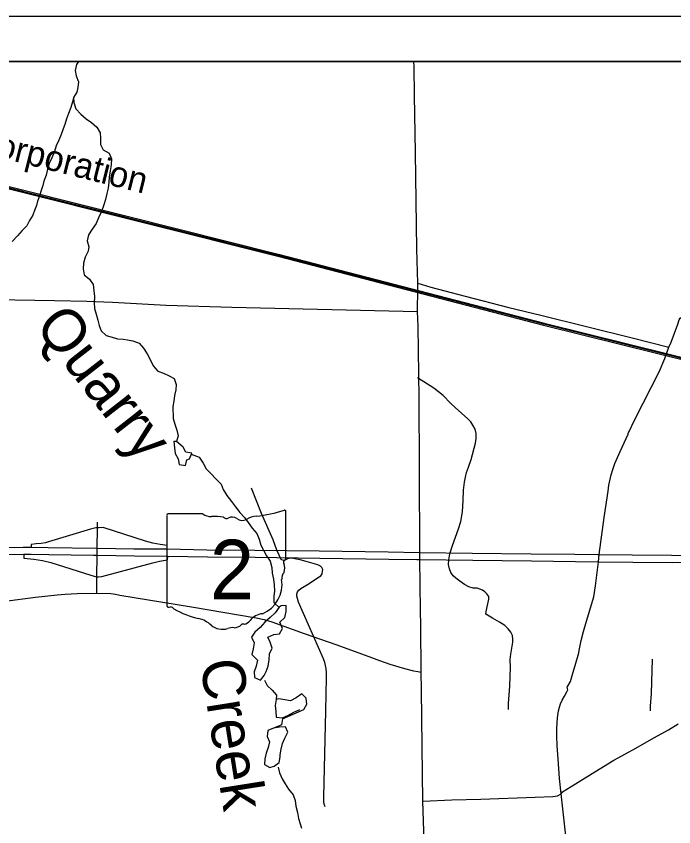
# Model space of a CAD drawing. Extents: x 0 to 34, y 0 to 22.
# Drawn here: x 10.012 to 11.47, y 8.768 to 10.565 of the extents above; entities that cross this region are included whole.
import ezdxf

# ---------------------------------------------------------------- set-up
doc = ezdxf.new("R2010")
doc.units = 0
for name, color, linetype in [('GM_X_City_Street', 7, 'Continuous'), ('GM_X_Corporation', 7, 'Continuous'), ('GM_X_County_Road', 7, 'Continuous'), ('GM_X_Interchange_Ramps', 7, 'Continuous'), ('GM_X_Minor_Lake', 7, 'Continuous'), ('GM_X_Minor_River', 7, 'Continuous'), ('GM_X_Minor_River_Text', 7, 'Continuous'), ('GM_X_Rail_Line', 7, 'Continuous'), ('GM_X_Rail_Line_Text', 7, 'Continuous'), ('GM_X_State_Location', 7, 'Continuous'), ('GM_X_State_Route', 7, 'Continuous'), ('GM_X_State_Shield', 7, 'Continuous'), ('GM_X_Township_Road', 7, 'Continuous'), ('SH_Cut_Line', 7, 'Continuous'), ('SH_Data', 7, 'Continuous')]:
    doc.layers.add(name, color=color, linetype=linetype)

msp = doc.modelspace()

# ---------------------------------------------------------------- linework, layer by layer
at = {"layer": 'GM_X_City_Street'}
for points in [[(11.103, 9.028), (11.1032, 9.0413), (11.1062, 9.0799), (11.1074, 9.1217), (11.1072, 9.1391), (11.1084, 9.1504), (11.1109, 9.164), (11.1131, 9.177), (11.1131, 9.1841), (11.1123, 9.1917), (11.1087, 9.1996), (11.1028, 9.207), (11.0949, 9.2141), (11.0831, 9.2217), (11.0681, 9.2308), (11.0531, 9.2397), (11.0535, 9.2453), (11.0578, 9.262), (11.0597, 9.2724), (11.0595, 9.2785), (11.0556, 9.2842), (11.0511, 9.2886), (11.046, 9.2923), (11.0337, 9.2972), (11.0253, 9.2972), (11.0155, 9.2999), (11.0059, 9.3053), (10.9951, 9.3122), (10.9865, 9.3188), (10.9808, 9.3245), (10.9757, 9.3318), (10.9725, 9.3395), (10.9705, 9.3493), (10.971, 9.3594), (10.9732, 9.3731), (10.9791, 9.3916), (10.9924, 9.4287), (10.9973, 9.4444), (11.001, 9.4658), (11.0027, 9.4914), (11.0039, 9.514), (11.0059, 9.5322), (11.0079, 9.5427), (11.0103, 9.5535), (11.0143, 9.5649), (11.0202, 9.5818), (11.0298, 9.6184), (11.0315, 9.6288), (11.0317, 9.6401), (11.0295, 9.6492), (11.0241, 9.6583), (11.0197, 9.6659), (11.0133, 9.6725), (10.9849, 9.6977), (10.9757, 9.7064), (10.9585, 9.7241), (10.9376, 9.7401), (10.9013, 9.7633)], [(10.6972, 8.8122), (10.695, 8.8185), (10.6942, 8.8234), (10.6941, 8.8348), (10.6987, 9.0253), (10.7001, 9.0991), (10.6999, 9.1104), (10.6994, 9.1185), (10.6977, 9.1254), (10.696, 9.1323), (10.693, 9.1406), (10.6603, 9.2156), (10.6382, 9.2662), (10.6357, 9.2738), (10.6343, 9.279), (10.6345, 9.2834), (10.6353, 9.2886), (10.6384, 9.2923), (10.6434, 9.296), (10.6613, 9.3075), (10.6797, 9.3198), (10.6871, 9.3242), (10.6901, 9.3289), (10.691, 9.3343), (10.6918, 9.3385), (10.6896, 9.3429), (10.6866, 9.3459), (10.681, 9.349), (10.6705, 9.3519), (10.6548, 9.3563), (10.6419, 9.3599), (10.6294, 9.3621), (10.6232, 9.3631), (10.6185, 9.3633), (10.6136, 9.3618), (10.6094, 9.3596), (10.6043, 9.3582), (10.6011, 9.3594), (10.5991, 9.3608), (10.5969, 9.3648), (10.5947, 9.3702), (10.59, 9.381), (10.5817, 9.4039), (10.5561, 9.4621), (10.5338, 9.5189)], [(11.4184, 9.0248), (11.4184, 9.0352), (11.4203, 9.0637), (11.4228, 9.1396)]]:
    msp.add_lwpolyline(points, dxfattribs=at)
at = {"layer": 'GM_X_Corporation'}
msp.add_lwpolyline([(12.0462, 8.3651), (12.0135, 9.4352), (12.0067, 9.6607), (11.5211, 9.7826), (11.5392, 9.8926), (11.8108, 9.8914), (11.7983, 10.4305), (11.9902, 10.4375), (11.9896, 10.4647), (7.3135, 10.4647)], dxfattribs=at)
at = {"layer": 'GM_X_County_Road'}
for p, q in [((10.902, 9.9603), (10.902, 9.9729)), ((10.9018, 9.9099), (10.902, 9.9603)), ((10.9094, 9.1109), (10.9087, 9.2133))]:
    msp.add_line(p, q, dxfattribs=at)
for points in [[(10.902, 9.9729), (10.9001, 10.0483), (10.8971, 10.2629), (10.8947, 10.389), (10.8939, 10.4522), (10.8937, 10.4647)], [(10.902, 9.9729), (10.9315, 9.9638), (11.0075, 9.9439), (11.1043, 9.9193), (11.1751, 9.9018), (11.3776, 9.8519), (11.4209, 9.8404), (11.4583, 9.8308), (11.4637, 9.8421), (11.4784, 9.8822), (11.4819, 9.8915), (11.4838, 9.8954), (11.4875, 9.8977), (11.4912, 9.8986), (11.4971, 9.8994), (11.5037, 9.8991)], [(9.5381, 9.9488), (9.7465, 9.9426), (9.9213, 9.9377), (10.0971, 9.9343), (10.1688, 9.9331), (10.2256, 9.9306), (10.3448, 9.924), (10.4898, 9.9195), (10.9018, 9.9099)], [(10.9063, 9.5564), (10.9063, 9.563), (10.9055, 9.7182), (10.903, 9.8777), (10.9018, 9.9099)], [(10.9068, 9.3605), (10.9067, 9.3763), (10.9063, 9.5564)], [(10.1912, 9.2861), (10.1909, 9.3224), (10.1914, 9.3701), (10.1916, 9.3858), (10.1922, 9.4305), (10.1926, 9.4434)], [(10.9087, 9.2133), (10.9084, 9.2485), (10.9068, 9.3605)], [(10.9133, 8.8248), (10.9118, 8.9464), (10.9104, 9.0716), (10.9094, 9.1109)], [(10.9274, 8.1427), (10.9276, 8.2181), (10.9246, 8.3546), (10.9237, 8.443), (10.9207, 8.5401), (10.9187, 8.6294), (10.9172, 8.7146), (10.9133, 8.8248)]]:
    msp.add_lwpolyline(points, dxfattribs=at)
at = {"layer": 'GM_X_Interchange_Ramps'}
for points in [[(10.1922, 9.4305), (10.1884, 9.4305), (10.177, 9.4279), (10.0838, 9.3994), (10.0772, 9.3978), (10.0676, 9.3963), (10.0562, 9.3952), (10.0454, 9.3937), (10.0454, 9.3878)], [(10.3468, 9.3839), (10.3468, 9.3912), (10.331, 9.3941), (10.3152, 9.3969), (10.299, 9.4013), (10.2047, 9.4314), (10.1961, 9.4309), (10.1922, 9.4305)], [(10.0289, 9.3724), (10.0291, 9.3638), (10.0514, 9.3614), (10.0704, 9.3586), (10.0889, 9.3537), (10.1779, 9.3259), (10.1849, 9.3235), (10.1909, 9.3224)], [(10.1909, 9.3224), (10.1946, 9.3222), (10.2023, 9.3226), (10.315, 9.3531), (10.3297, 9.357), (10.3478, 9.3594), (10.348, 9.3681)]]:
    msp.add_lwpolyline(points, dxfattribs=at)
at = {"layer": 'GM_X_Minor_Lake'}
for points in [[(10.3676, 9.6223), (10.3619, 9.6219), (10.3631, 9.6082), (10.3648, 9.5956), (10.3709, 9.5835), (10.3737, 9.5714), (10.3874, 9.5688), (10.3907, 9.5814)], [(10.3676, 9.6223), (10.3619, 9.6219), (10.3631, 9.6082), (10.3648, 9.5956), (10.3709, 9.5835), (10.3737, 9.5714), (10.3874, 9.5688), (10.3907, 9.5814)], [(10.3907, 9.5814), (10.396, 9.5837), (10.4012, 9.5963), (10.3883, 9.5985), (10.3821, 9.6095), (10.3675, 9.6223)], [(10.3907, 9.5814), (10.396, 9.5837), (10.4012, 9.5963), (10.3883, 9.5985), (10.3821, 9.6095), (10.3676, 9.6223)], [(10.5998, 9.258), (10.5952, 9.2549), (10.5862, 9.2426), (10.5749, 9.2319), (10.5636, 9.2219), (10.5527, 9.21), (10.541, 9.1996), (10.5335, 9.1881), (10.5393, 9.176), (10.5375, 9.1626), (10.5345, 9.1497), (10.5468, 9.1372), (10.5442, 9.1243), (10.5394, 9.1113), (10.5403, 9.0987), (10.554, 9.0928), (10.5619, 9.1035)], [(10.5956, 9.2533), (10.5952, 9.2549), (10.5862, 9.2426), (10.5749, 9.2319), (10.5636, 9.2219), (10.5527, 9.21), (10.541, 9.1996), (10.5335, 9.1881), (10.5393, 9.176), (10.5375, 9.1626), (10.5345, 9.1497), (10.5468, 9.1372), (10.5442, 9.1243), (10.5394, 9.1113), (10.5403, 9.0987), (10.554, 9.0928), (10.5619, 9.1035)], [(10.5619, 9.1035), (10.5664, 9.1123), (10.5709, 9.1241), (10.5726, 9.1378), (10.5733, 9.1515), (10.5793, 9.1642), (10.5754, 9.1771), (10.5696, 9.1884), (10.5832, 9.1939), (10.5957, 9.1955), (10.6021, 9.2077), (10.5963, 9.2218), (10.6076, 9.2321), (10.6105, 9.2451), (10.6108, 9.2588), (10.5998, 9.258)], [(10.5892, 9.0596), (10.5886, 9.0501), (10.586, 9.0367), (10.5876, 9.0238), (10.5885, 9.0109), (10.6022, 9.0099), (10.6143, 9.0149), (10.6276, 9.0219), (10.6408, 9.0277)], [(10.6169, 9.0137), (10.6499, 9.0282), (10.6563, 9.0397), (10.6547, 9.0534), (10.6451, 9.0624), (10.633, 9.0539), (10.6205, 9.047), (10.6076, 9.0491), (10.5946, 9.0517)], [(10.6022, 9.0072), (10.6499, 9.0282), (10.6563, 9.0397), (10.6547, 9.0534), (10.6451, 9.0624), (10.633, 9.0539), (10.6205, 9.047), (10.6076, 9.0491), (10.5946, 9.0517)], [(10.5946, 9.0517), (10.5886, 9.0501), (10.586, 9.0367), (10.5876, 9.0238), (10.5885, 9.0109), (10.6022, 9.0099), (10.6169, 9.0137)], [(10.6004, 8.9943), (10.5955, 8.9919), (10.5822, 8.9869), (10.5697, 8.9814), (10.5687, 8.9685), (10.5737, 8.9563), (10.5708, 8.9441), (10.5664, 8.9312), (10.563, 8.919), (10.5628, 8.906), (10.5742, 8.8996), (10.5837, 8.9024), (10.595, 8.9109), (10.5976, 8.9231)], [(10.5955, 8.9885), (10.5822, 8.9869), (10.5697, 8.9814), (10.5687, 8.9685), (10.5737, 8.9563), (10.5708, 8.9441), (10.5664, 8.9312), (10.563, 8.919), (10.5628, 8.906), (10.5742, 8.8996), (10.5837, 8.9024), (10.595, 8.9109), (10.5976, 8.9231)], [(10.5976, 8.9231), (10.5972, 8.9276), (10.5993, 8.9402), (10.6023, 8.9524), (10.6079, 8.9643), (10.6139, 8.9776), (10.6092, 8.9894), (10.5955, 8.9885)]]:
    msp.add_lwpolyline(points, dxfattribs=at)
at = {"layer": 'GM_X_Minor_River'}
for points in [[(10.1505, 10.4647), (10.146, 10.4578), (10.1426, 10.4441), (10.145, 10.4323), (10.1501, 10.4194), (10.149, 10.4065), (10.1465, 10.3966), (10.139, 10.3847)], [(10.139, 10.3847), (10.1371, 10.3748), (10.1334, 10.3626), (10.1282, 10.3492), (10.1238, 10.337), (10.1201, 10.3244), (10.116, 10.3149), (10.1119, 10.3026), (10.107, 10.29), (10.1011, 10.2774), (10.0974, 10.2652), (10.0914, 10.2507), (10.085, 10.2381), (10.0817, 10.2255), (10.0784, 10.2125), (10.0736, 10.1988), (10.071, 10.1892), (10.0669, 10.1759), (10.0636, 10.1656), (10.0595, 10.1549), (10.0569, 10.1454), (10.0524, 10.1339), (10.0487, 10.124), (10.042, 10.1121), (10.0356, 10.1003), (10.0251, 10.0899), (10.0153, 10.078), (10.0036, 10.065)], [(10.139, 10.3847), (10.1398, 10.3731), (10.1445, 10.3593), (10.1552, 10.3479), (10.1675, 10.3374), (10.1793, 10.3291), (10.1908, 10.3186), (10.1985, 10.3065), (10.199, 10.2943), (10.1987, 10.2806), (10.2053, 10.2685), (10.2183, 10.2614), (10.2237, 10.2485), (10.223, 10.2355), (10.2201, 10.2218), (10.2183, 10.2081), (10.2173, 10.1967), (10.2159, 10.1837), (10.2133, 10.1715), (10.21, 10.1585), (10.2063, 10.1463), (10.2015, 10.1322), (10.1944, 10.1181), (10.1891, 10.1051), (10.1805, 10.0928), (10.1726, 10.0802), (10.1697, 10.0672), (10.1728, 10.0536), (10.1718, 10.044), (10.165, 10.031), (10.161, 10.0177), (10.1603, 10.0047), (10.1631, 9.9918), (10.1749, 9.982), (10.1827, 9.9699), (10.1843, 9.9559), (10.1855, 9.9433), (10.1853, 9.9296), (10.1857, 9.9167), (10.1893, 9.9045), (10.1932, 9.8913), (10.1963, 9.8795), (10.2002, 9.867), (10.2117, 9.8572), (10.2247, 9.8531), (10.2365, 9.8498), (10.249, 9.8488), (10.2585, 9.8473), (10.2707, 9.8452), (10.2844, 9.8403), (10.2944, 9.829), (10.3025, 9.8161), (10.3095, 9.8021), (10.3156, 9.79), (10.326, 9.7783), (10.3386, 9.7735), (10.3512, 9.7679), (10.3623, 9.7615), (10.3669, 9.7486), (10.3659, 9.7368), (10.3629, 9.7242), (10.3615, 9.7113), (10.3597, 9.6998), (10.3599, 9.6732), (10.3635, 9.6607), (10.3685, 9.6474), (10.3713, 9.6345), (10.3676, 9.6223)], [(10.4002, 9.594), (10.4177, 9.587), (10.4269, 9.5741), (10.4335, 9.5612), (10.4442, 9.5503), (10.4549, 9.539), (10.4668, 9.5277), (10.4711, 9.5155), (10.4788, 9.5027), (10.4896, 9.4891), (10.4984, 9.4774), (10.508, 9.4649), (10.518, 9.4539), (10.5264, 9.4422), (10.5353, 9.4301), (10.5453, 9.418), (10.5507, 9.4055), (10.5546, 9.3926), (10.5669, 9.3684), (10.575, 9.3567), (10.5786, 9.343), (10.5798, 9.3304), (10.5826, 9.3168), (10.5842, 9.3042), (10.5847, 9.2913), (10.5829, 9.2783), (10.583, 9.2654), (10.5956, 9.2533)], [(10.5624, 9.0932), (10.5682, 9.0815), (10.5793, 9.0709), (10.5892, 9.0596)], [(10.6022, 9.0072), (10.6004, 8.9943)], [(10.5925, 8.9002), (10.5956, 8.8873), (10.6014, 8.8744), (10.6083, 8.863), (10.6157, 8.8513), (10.6264, 8.8392), (10.6307, 8.826), (10.6323, 8.8134), (10.6359, 8.7994), (10.6382, 8.7865), (10.6414, 8.7743), (10.6445, 8.7648)]]:
    msp.add_lwpolyline(points, dxfattribs=at)
at = {"layer": 'GM_X_Rail_Line'}
for points in [[(8.873, 10.4647), (9.6892, 10.2593), (10.5917, 10.0331), (11.1811, 9.8802), (12.0186, 9.6724), (12.8863, 9.4545), (13.1526, 9.3886), (13.8266, 9.2172), (14.1135, 9.147)], [(8.8821, 10.4647), (9.6898, 10.2615), (10.5923, 10.0354), (11.1817, 9.8825), (12.0192, 9.6747), (12.8869, 9.4568), (13.1532, 9.3908), (13.8271, 9.2194), (14.1135, 9.1494)], [(9.1167, 10.404), (9.1537, 10.3972), (9.6904, 10.2638), (10.5928, 10.0376), (11.1823, 9.8847), (12.0197, 9.6769), (12.8874, 9.459), (13.1538, 9.3931), (13.8277, 9.2217), (14.1135, 9.1518)]]:
    msp.add_lwpolyline(points, dxfattribs=at)
at = {"layer": 'GM_X_State_Route'}
for points in [[(9.7425, 9.3695), (9.7435, 9.3696), (9.7476, 9.37), (9.8474, 9.3802), (9.8958, 9.3833), (9.9408, 9.3858), (9.9814, 9.387), (10.0276, 9.3882), (10.0454, 9.3878), (10.083, 9.3872), (10.1902, 9.3858), (10.1916, 9.3858), (10.2729, 9.3845), (10.3468, 9.3839), (10.4348, 9.3823), (10.5409, 9.3814), (10.6836, 9.3794), (10.8367, 9.3773), (10.9055, 9.3763), (10.9061, 9.3763)], [(9.7467, 9.3541), (9.8487, 9.3644), (9.8971, 9.3675), (9.9421, 9.3701), (9.9827, 9.3713), (10.0289, 9.3724), (10.0454, 9.372), (10.0843, 9.3714), (10.1832, 9.3702)], [(10.1832, 9.3702), (10.1914, 9.3701), (10.2742, 9.3687), (10.348, 9.3681), (10.436, 9.3666), (10.5421, 9.3656), (10.6849, 9.3636), (10.8379, 9.3615), (10.8998, 9.3606)], [(10.8998, 9.3606), (10.9068, 9.3605), (11.024, 9.3592), (11.1544, 9.3576), (11.2517, 9.3564), (11.3026, 9.3557), (11.3789, 9.3549), (11.466, 9.3541), (11.6874, 9.3586), (11.8536, 9.3616), (11.8607, 9.3617), (11.929, 9.3638), (12.0148, 9.3655)], [(10.9061, 9.3763), (10.9067, 9.3763), (11.0227, 9.3749), (11.1532, 9.3734), (11.2505, 9.3722), (11.3013, 9.3715), (11.3046, 9.3714), (11.3776, 9.3706), (11.4648, 9.3699), (11.5638, 9.3685), (11.6824, 9.3704), (11.8606, 9.3743)]]:
    msp.add_lwpolyline(points, dxfattribs=at)
at = {"layer": 'GM_X_State_Shield'}
for p, q in [((10.3461, 9.4584), (10.3461, 9.2583)), ((10.4259, 9.4619), (10.3487, 9.4619)), ((10.6098, 9.3622), (10.6098, 9.4668)), ((10.6098, 9.3622), (10.6098, 9.3622))]:
    msp.add_line(p, q, dxfattribs=at)
for centre, radius, start, end in [((10.5159, 9.7347), 0.2796, 275.8445, 288.9065), ((10.6069, 9.4673), 0.00294, 351.8621, 97.738), ((10.3491, 9.4589), 0.00305, 98.1301, 188.1301), ((10.4443, 9.4851), 0.0296, 231.6195, 271.1119), ((10.4541, 9.3495), 0.1064, 80.4867, 94.9883), ((10.4783, 9.4599), 0.00855, 219.7921, 297.1024), ((10.4908, 9.4368), 0.0178, 54.4667, 119.1411), ((10.5138, 9.4685), 0.0214, 233.8562, 294.8282), ((10.5515, 9.4008), 0.0563, 97.3462, 120.7689), ((10.6067, 9.3617), 0.00314, 289.6038, 7.7341), ((10.6091, 9.3545), 0.00454, 107.944, 210.337), ((10.5802, 9.3412), 0.0273, 340.033, 23.6496), ((10.6203, 9.3183), 0.0198, 136.8065, 186.9296), ((10.5315, 9.305), 0.0699, 292.3089, 8.9858), ((10.3492, 9.2579), 0.00308, 171.9584, 258.3066), ((10.3496, 9.2784), 0.0235, 267.339, 280.6039), ((10.3545, 9.2468), 0.00848, 29.7484, 93.2717), ((10.4615, 9.4266), 0.2019, 240.4129, 257.1985), ((10.561, 9.2021), 0.0383, 94.4031, 142.5768), ((10.4013, 9.1684), 0.0632, 47.1842, 75.836), ((10.5151, 9.2114), 0.00601, 65.7517, 132.6484), ((10.5125, 9.2389), 0.0226, 282.8732, 323.2771), ((10.4696, 9.2458), 0.0401, 230.7004, 286.2918), ((10.4928, 9.1766), 0.0329, 85.6951, 111.2099), ((10.4957, 9.2308), 0.0214, 268.777, 315.5493)]:
    msp.add_arc(centre, radius, start, end, dxfattribs=at)
at = {"layer": 'GM_X_Township_Road'}
for points in [[(11.3683, 9.6385), (11.3687, 9.6395), (11.3844, 9.6722), (11.4019, 9.707), (11.4198, 9.7421), (11.4376, 9.7762), (11.4497, 9.8057), (11.4583, 9.8308)], [(11.2601, 9.159), (11.2646, 9.181), (11.2696, 9.201), (11.2763, 9.2241), (11.2921, 9.2779), (11.2958, 9.3018), (11.3026, 9.3557), (11.3046, 9.3714), (11.3154, 9.4535), (11.3239, 9.5123), (11.326, 9.5249), (11.3286, 9.5383), (11.3312, 9.5485), (11.3345, 9.56), (11.3393, 9.5734), (11.3508, 9.6001), (11.3683, 9.6385)], [(9.7436, 9.2652), (9.7937, 9.2623), (9.8663, 9.2591), (9.8975, 9.2588), (9.925, 9.2606), (9.954, 9.2642), (9.9874, 9.2684), (10.0553, 9.2773), (10.103, 9.2824), (10.1204, 9.2837), (10.1474, 9.2853), (10.1912, 9.2861)], [(10.1912, 9.2861), (10.222, 9.2849), (10.232, 9.2834), (10.2417, 9.2818), (10.4006, 9.2556), (10.5444, 9.2314), (10.562, 9.2278), (10.5791, 9.2226), (10.6501, 9.1967), (10.7231, 9.1711), (10.7772, 9.1512), (10.7995, 9.1431), (10.8175, 9.1367), (10.8403, 9.1286), (10.873, 9.1192), (10.8924, 9.1141), (10.9023, 9.1119), (10.9094, 9.1109)], [(11.243, 8.6358), (11.22, 8.8408), (11.2164, 8.8754), (11.2134, 8.9185), (11.2114, 8.9472), (11.2102, 8.9698), (11.2102, 8.9869), (11.2119, 9.0093), (11.2142, 9.0251), (11.2164, 9.0335), (11.2188, 9.0404), (11.2226, 9.049), (11.2276, 9.0578), (11.2329, 9.0669), (11.2348, 9.0716), (11.2332, 9.0778), (11.2357, 9.081), (11.2407, 9.0898), (11.2462, 9.1082), (11.251, 9.1258), (11.2589, 9.1533), (11.2601, 9.159)], [(10.9133, 8.8248), (10.978, 8.8277), (11.0419, 8.8295), (11.1621, 8.8335), (11.2019, 8.8351), (11.2117, 8.8368), (11.22, 8.8408), (11.2233, 8.8458), (11.2421, 8.857), (11.304, 8.8955), (11.3368, 8.916), (11.3787, 8.9389), (11.4272, 8.9659), (11.4579, 8.9831), (11.479, 8.9959)]]:
    msp.add_lwpolyline(points, dxfattribs=at)
at = {"layer": 'SH_Cut_Line'}
msp.add_lwpolyline([(14.1135, 10.4647), (8.6408, 10.4647)], dxfattribs=at)
at = {"layer": 'SH_Data'}
for p, q in [((7.2135, 10.5647), (14.2135, 10.5647)), ((7.3135, 10.4647), (14.1135, 10.4647))]:
    msp.add_line(p, q, dxfattribs=at)

# ---------------------------------------------------------------- texts
at = {"layer": 'GM_X_Minor_River_Text'}
for s, rotation, p in [('Quarry', 307.9937, (10.0511, 9.8777)), ('Creek', 278.9941, (10.4193, 9.1336))]:
    msp.add_text(s, height=0.09475, rotation=rotation, dxfattribs=at).set_placement(p)
at = {"layer": 'GM_X_Rail_Line_Text'}
msp.add_text('Corporation', height=0.056629, rotation=345.9899, dxfattribs=at).set_placement((9.9113, 10.2671))
at = {"layer": 'GM_X_State_Location'}
for s in ['s', 'r']:
    msp.add_text(s, height=0.000189, dxfattribs=at).set_placement((10.475, 9.3451))
msp.add_text('2', height=0.000189, rotation=0, dxfattribs=at).set_placement((10.4465, 9.3313))
at = {"layer": 'GM_X_State_Shield'}
msp.add_text('2', height=0.1318, dxfattribs=at).set_placement((10.4414, 9.2724))

doc.saveas('drawing.dxf')
